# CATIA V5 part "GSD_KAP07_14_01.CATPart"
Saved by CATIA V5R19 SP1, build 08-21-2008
Part number: GSD_KAP07_14_01
Definition: Beispielmodell für die Funktion Eckenverrundung / EdgeFillet
Description: CATIA V5 Flächenmodellierung  Copyright (c) 2009 Maik Hertha IT Consultants
Bounding box of the stored display mesh (mm): x -56.552 to 55.86, y -41.359 to 65.732, z -10 to 30
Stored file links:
  \GSD_BUCH_UEBUNG\GSD_KAP07_14_01.CATPart
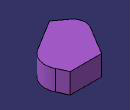
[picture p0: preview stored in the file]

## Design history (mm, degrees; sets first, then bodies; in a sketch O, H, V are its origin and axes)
AxisSystem1 "Absolute Axis System": origin (0, 0, 0), X (1, 0, 0), Y (0, 1, 0), Z (0, 0, 1)
Set1 "Edge Support"
  Plane1: type Equation, A 0, B 0, C 1, Length -10
  Point1: type OnPlane, Support Plane1, Direction (1, 0, 0), H 10, V 10
  Sketch1 on Plane1, origin (10, 10, -10), H (0, 1, 0), V (-1, 0, 0)
    line L1 (-51.3593, 33.255) -> (-33.8184, 56.4068)
    arc A1 centre (-13.4029, 40.9391) radius 25.6134 from (-33.8184, 56.4068) to (-0.1418, 62.8523) cw
    line L2 (-0.1418, 62.8523) -> (55.7324, 29.0392)
    line L3 (55.7324, 29.0392) -> (55.7324, -32.7926)
    line L4 (55.7324, -32.7926) -> (35.6076, -42.197)
    arc A2 centre (19.1105, -6.8942) radius 38.9672 from (35.6076, -42.197) to (-14.0743, -27.3201) cw
    line L5 (-14.0743, -27.3201) -> (-51.3593, 33.255)
    curve C1
    construction line L6 (-1.4464, -47.8359) -> (-25.97, -7.9936)
    angle L5 L6 = 0
    tangency: A1 L1, L2 A1, A2 L4, L6 A2, A2 L5
    vertical: L3 V
  Split1: ToCut Plane1, Cutting Sketch1.C1
  Extrude1: Lim1 40, Lim2 0, Element1 Split1, Direction Plane1
Set2 "Edge 1"
  DatumSurface1: linked copy from another document
Body1 (main body)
